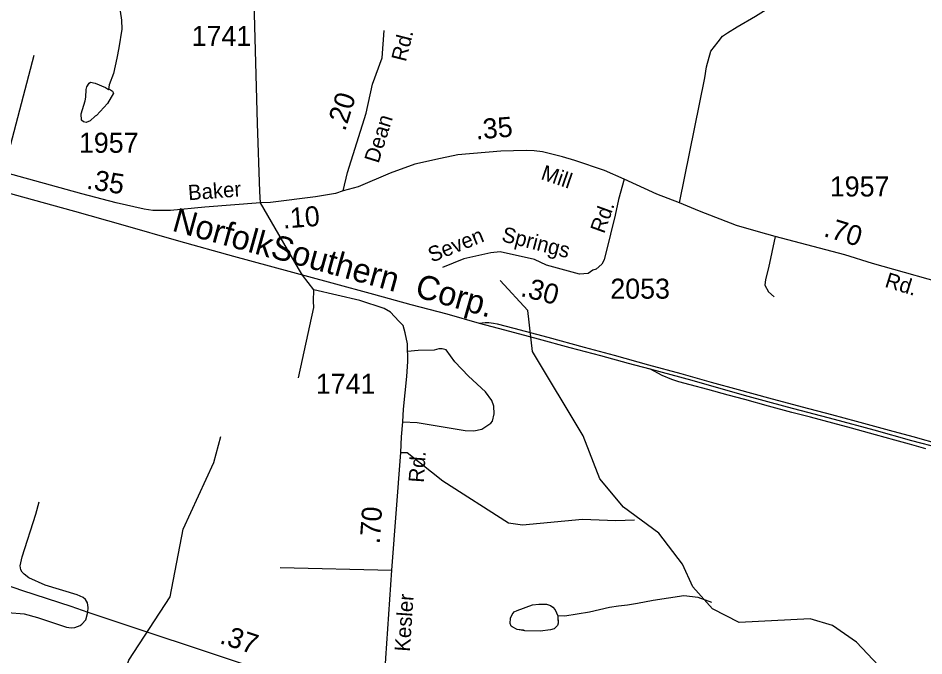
# Model space of a CAD drawing. Extents: x 1473865 to 1648260, y 639067 to 773536.
# Drawn here: x 1505606 to 1511254, y 721780 to 725760 of the extents above; entities that cross this region are included whole.
import ezdxf

# ---------------------------------------------------------------- set-up
doc = ezdxf.new("R2010")
doc.units = 0
for name, color, linetype in [('Exist Hydrographic Creek Single Shore', 7, 'Continuous'), ('Exist Hydrographic Misc Water Feature', 7, 'Continuous'), ('Exist Railroad Mainline', 7, 'Continuous'), ('Exist Railroad Mainline Label', 7, 'Continuous'), ('Exist Road Non-System Type 51', 7, 'Continuous'), ('Exist Road Primary US Attributed', 7, 'Continuous'), ('Exist Road Primary US Mileage Hundredths English Label', 7, 'Continuous'), ('Exist Road Secondary Mileage Hundredths English Label', 7, 'Continuous'), ('Exist Road Secondary Type 51 Attributed', 7, 'Continuous'), ('Exist Road Secondary Type 51 Label', 7, 'Continuous'), ('Exist Road Secondary Type 51 Number Label', 7, 'Continuous')]:
    doc.layers.add(name, color=color, linetype=linetype)

msp = doc.modelspace()

# ---------------------------------------------------------------- linework, layer by layer
at = {"layer": 'Exist Hydrographic Creek Single Shore'}
msp.add_lwpolyline([(1510972.3, 721721.4), (1510833.4, 721865.3), (1510685.3, 721970.1), (1510544.4, 722012.3), (1510102.4, 721988.4), (1509936.3, 722073.8), (1509814.4, 722210.9), (1509749.4, 722353.3), (1509602.4, 722546.6), (1509380.3, 722708.7), (1509233.4, 722885.6), (1509129.3, 723153.6), (1508813.3, 723678.7), (1508784.3, 723935.3), (1508612.4, 724122.6)], dxfattribs=at)
at = {"layer": 'Exist Hydrographic Misc Water Feature'}
for points in [[(1506242.9, 725802.3), (1506249.9, 725746.2), (1506252.8, 725690.1), (1506234.8, 725574.6), (1506221.7, 725510.9), (1506199.9, 725415.3), (1506174.6, 725343.9), (1506168.6, 725314.8)], [(1506168.6, 725314.8), (1506176.1, 725315.9), (1506194, 725303.5), (1506200.7, 725292), (1506162.5, 725226.2), (1506095.2, 725151.5), (1506087.1, 725147.7), (1506054.6, 725118.3), (1506030.5, 725108.8), (1506014.5, 725113.1), (1506000.7, 725123.3), (1505999.4, 725163.3), (1506024.8, 725242.8), (1506029.2, 725266.7), (1506030.1, 725314.6), (1506034.3, 725330.5), (1506048.8, 725354.3), (1506056.9, 725360.1), (1506086.8, 725353.5), (1506150.3, 725326.3), (1506168.6, 725314.8)], [(1506809.2, 713697.5), (1506731.2, 713991.2), (1506727.2, 714283.4), (1506386.2, 714772.9), (1506100.3, 716137.6), (1506090.2, 716502.2), (1506115.2, 717496.3), (1506265.2, 718451.7), (1506315.3, 718933.3), (1506320.3, 719268), (1506235.3, 719627.5), (1506154.2, 719770.3), (1506083.3, 720021.2), (1506054.2, 720271.3), (1506093.3, 720615.2), (1506216.2, 720993.5), (1506221.3, 721252.7), (1506206.3, 721387.5), (1506226.3, 721544.8), (1506296.3, 721753.4), (1506553.2, 722148.7), (1506635.3, 722570.5), (1506826.3, 722986.8), (1506870.2, 723150.1)], [(1508971.6, 722029.3), (1508971.6, 722013.2), (1508973.2, 721985.2), (1508968.8, 721969.3), (1508948.5, 721949.7), (1508926.4, 721942.1), (1508862.2, 721935.3), (1508766.3, 721937.1), (1508758.4, 721941.3), (1508718.4, 721946), (1508686.7, 721960.7), (1508680.8, 721966.8), (1508675, 721982.8), (1508675.6, 722014.8), (1508686.1, 722038.6), (1508700.3, 722054.3), (1508718.5, 722063.9), (1508813.1, 722098.1), (1508853.2, 722103.4), (1508901.2, 722102.4), (1508925.1, 722094), (1508940.9, 722083.7), (1508954.6, 722067.5), (1508971.6, 722029.3)], [(1508971.6, 722029.3), (1508973.2, 721985.2), (1508968.8, 721969.3), (1508948.5, 721949.7), (1508926.4, 721942.1), (1508862.2, 721935.3), (1508766.3, 721937.1), (1508718.4, 721946), (1508686.7, 721960.7), (1508680.8, 721966.8), (1508675, 721982.8), (1508675.6, 722014.8), (1508686.1, 722038.6), (1508700.3, 722054.3), (1508718.5, 722063.9), (1508813.1, 722098.1), (1508853.2, 722103.4), (1508901.2, 722102.4), (1508925.1, 722094), (1508940.9, 722083.7), (1508954.6, 722067.5), (1508971.6, 722029.3)], [(1509931.8, 722113.1), (1509846.2, 722144.5), (1509758.3, 722154.2), (1509565.8, 722125.9), (1509469.4, 722107.7), (1509405.2, 722096.9), (1509349.1, 722090), (1509292.9, 722083.1), (1509168.4, 722053.4), (1509015.9, 722028.4), (1508971.6, 722029.3)]]:
    msp.add_lwpolyline(points, dxfattribs=at)
at = {"layer": 'Exist Railroad Mainline'}
for points in [[(1505368.3, 724718.2), (1505633.1, 724644.2), (1505957.7, 724555.6), (1506258.5, 724469.3), (1506607.1, 724370.2), (1506949.6, 724275.2), (1507294.2, 724180.4), (1507563.1, 724108.6), (1507822, 724036.7), (1508055, 723973.4), (1508280.1, 723914.2), (1508481.3, 723857.3)], [(1508481.3, 723857.3), (1508518.8, 723861.2), (1508541.4, 723860.3), (1508569.7, 723856.9), (1508593.2, 723851.7), (1508696.8, 723826.2), (1508909.9, 723769), (1509135, 723705.9), (1509322.9, 723656.2), (1509537.4, 723596.1), (1509738.6, 723543.2), (1509927.8, 723488.4), (1510097.1, 723442.1), (1510286.4, 723391.3), (1510495.6, 723334.2), (1510678.9, 723285.7), (1510833.1, 723244), (1511037.3, 723188.4), (1511184.8, 723148.4), (1511362.1, 723099.8)], [(1508481.3, 723857.3), (1508638.7, 723814.9), (1508849.9, 723758), (1509047.1, 723705.2), (1509238.4, 723654.3), (1509409.5, 723607.9), (1509545.1, 723571.9)], [(1511265.7, 723073.1), (1511164, 723100.6), (1511072.5, 723126.1), (1510952.9, 723159.7), (1510802.6, 723200.4), (1510686, 723231.5), (1510547.1, 723268.9), (1510431, 723299.3), (1510285.6, 723339.3), (1510138.3, 723379.4), (1510034.6, 723407), (1509907.3, 723442.7), (1509797.6, 723472.4), (1509726, 723491.4), (1509682, 723505.9), (1509622.5, 723530.9), (1509545.1, 723571.9)], [(1509545.1, 723571.9), (1509808, 723500.2), (1510132.7, 723407.6), (1510401.5, 723333.7), (1510695.5, 723256.7), (1510943.3, 723189.9), (1511176.5, 723124.6), (1511353.6, 723078), (1511558.8, 723019), (1511731.1, 722972.3), (1511855.7, 722938.8), (1512009, 722898.9), (1512118.6, 722868.8), (1512228.1, 722839.4), (1512327.8, 722812)]]:
    msp.add_lwpolyline(points, dxfattribs=at)
at = {"layer": 'Exist Road Non-System Type 51'}
for p, q in [((1505514.2, 724798.1), (1505706.4, 725529.2)), ((1507240.3, 722331.1), (1507936.9, 722315.8))]:
    msp.add_line(p, q, dxfattribs=at)
for points in [[(1509731.3, 724607.2), (1509889.3, 725386.6), (1509899.2, 725456.3), (1509924.8, 725553.8), (1509972.5, 725612.1), (1509999, 725647.8), (1510030, 725669), (1510089.7, 725704.6), (1510204.8, 725771.4), (1510327.1, 725849.7), (1510499.9, 725960.2), (1510875.2, 726202), (1511051.4, 726324.4), (1511088.4, 726354.2), (1511133.9, 726395.5), (1511173.1, 726485.8), (1511181.9, 726547.6), (1511185.8, 726680.2), (1511193.6, 726859), (1511191.7, 727024.9), (1511205.7, 727329.3)], [(1510327.9, 724397.2), (1510286, 724200.7), (1510266.7, 724128.3), (1510263.5, 724092.8), (1510284.4, 724051), (1510319.8, 724020.4)], [(1507354.2, 723516.3), (1507450.9, 723954.9), (1507447.9, 723994.2), (1507451, 724065)], [(1508004.2, 723241.2), (1508094.2, 723235.8), (1508393.5, 723187.7), (1508447.3, 723184.9), (1508497.5, 723194.3), (1508554.1, 723233.3), (1508564.2, 723245.3), (1508574.9, 723291.1), (1508573.5, 723339.2), (1508560, 723373.3), (1508520.9, 723428.6), (1508415.1, 723525.4), (1508330.4, 723616.1), (1508303.2, 723652.4), (1508274.4, 723689.2), (1508250.5, 723695.7), (1508230.5, 723695.9), (1508200.3, 723688.3), (1508100.7, 723685.7), (1508034.2, 723679.7)], [(1507992.7, 723050), (1508031.2, 723050), (1508254.8, 722872.5), (1508663.4, 722610.1), (1508752.1, 722598.6), (1509126.1, 722633.3), (1509334.2, 722625.6), (1509449.9, 722629.4)], [(1506040, 722053), (1506041.8, 722081.6), (1506038.4, 722111.7), (1506026.6, 722131.9), (1506010.9, 722144.3), (1505973.2, 722160.8), (1505774.3, 722222.1), (1505673, 722267.9), (1505643.4, 722290.4), (1505631.7, 722302.6), (1505623.8, 722316.8), (1505618.3, 722342.7), (1505631.2, 722398.5), (1505715.6, 722665.1), (1505736.8, 722740.7)]]:
    msp.add_lwpolyline(points, dxfattribs=at)
at = {"layer": 'Exist Road Primary US Attributed'}
for points in [[(1503181.7, 723021.6), (1503536.3, 722902.2), (1504318.6, 722637.3), (1504517.7, 722580.2), (1504564.7, 722564.5), (1505188.3, 722343), (1505634, 722188.7), (1505934.6, 722091), (1506040, 722053)], [(1506040, 722053), (1507097.1, 721702.1), (1507789.7, 721464.4), (1507881.3, 721435.2)]]:
    msp.add_lwpolyline(points, dxfattribs=at)
at = {"layer": 'Exist Road Secondary Type 51 Attributed'}
for points in [[(1507117.3, 724607.4), (1507112.4, 724677.6), (1507098.1, 725101.7), (1507065.1, 726319.8), (1507058.9, 726452), (1507059.4, 726486), (1507066.3, 726549.9), (1507078.4, 726639), (1507093.8, 726718.3), (1507128.3, 726802.2), (1507153, 726849.8), (1507215.9, 726957.1), (1507303.5, 727078.4), (1507631.9, 727569.8), (1507894.8, 727943.9), (1508024.1, 728128), (1508391.7, 728684.9)], [(1507632.8, 724682.2), (1507660, 724796.2), (1507776.5, 725165.8), (1507816.4, 725347.6), (1507875.2, 725513.1), (1507889.5, 725682.2)], [(1509386.1, 724755), (1509261.7, 724809.1), (1509078.7, 724871.8), (1509001.1, 724894.8), (1508875.4, 724924.5), (1508824.8, 724932.2), (1508773.6, 724934), (1508615.4, 724929.1), (1508347.2, 724906.9), (1508239.1, 724883.6), (1508079.1, 724848.7), (1507926.8, 724793), (1507726.1, 724707.4), (1507632.8, 724682.2)], [(1507117.3, 724607.4), (1506769.4, 724581.2), (1506556.7, 724559.3), (1506446.8, 724558.9), (1506391, 724567.7), (1506217.5, 724608.2), (1506004.3, 724663.1), (1505514.2, 724798.1)], [(1509386.1, 724755), (1509350.7, 724627.9), (1509328.2, 724529.8), (1509299.3, 724411.5), (1509260, 724251.2), (1509245.7, 724225.5), (1509211.3, 724194), (1509190, 724186.3), (1509161.1, 724165.4), (1509106.4, 724162.1), (1508901.2, 724218.4), (1508825.2, 724253.8), (1508613, 724302.5), (1508554.8, 724295.3), (1508386.3, 724257.7), (1508252.3, 724203.5)], [(1512599.7, 723546.3), (1512526.7, 723585.8), (1512363.6, 723682.9), (1512246.6, 723747.3), (1512119.4, 723811.1), (1511959.3, 723889), (1511735.8, 723986.9), (1511595.7, 724035.2), (1511480.4, 724074.4), (1510933.5, 724229.7), (1510762.2, 724282.1), (1510327.9, 724397.2), (1510223.3, 724426.2), (1510085.8, 724465.5), (1509855.1, 724554.6), (1509731.3, 724607.2), (1509589.2, 724661.8), (1509386.1, 724755)], [(1507632.8, 724682.2), (1507585.9, 724666.5), (1507460, 724645.3), (1507179.4, 724608.6), (1507117.3, 724607.4)], [(1507378.9, 724155.7), (1507355.5, 724196.6), (1507117.3, 724607.4)], [(1507881.3, 721435.2), (1507899.8, 721767), (1507936.9, 722315.8), (1507992.7, 723050), (1507997.6, 723148.2), (1508004.2, 723241.2), (1508009.4, 723319.2), (1508030.1, 723522.7), (1508035.4, 723616.6), (1508035, 723726.7), (1508020.1, 723796.1), (1508006.4, 723841), (1507979.7, 723868.6), (1507927.6, 723925.7), (1507888.6, 723947.3), (1507736.8, 723998.8), (1507451, 724065), (1507378.9, 724155.7)], [(1505541.6, 722052.1), (1505643.2, 722042.4), (1505726.8, 722018.9), (1505907.9, 721959.8), (1505935.8, 721955.5), (1505959.9, 721957), (1505992, 721970.6), (1506004.1, 721978.3), (1506028.7, 722005.8), (1506040, 722053)]]:
    msp.add_lwpolyline(points, dxfattribs=at)

# ---------------------------------------------------------------- texts
at = {"layer": 'Exist Railroad Mainline Label'}
for s, rotation, p in [('Norfolk', 344.5017, (1506559.7, 724434.4)), ('Southern', 344.4864, (1507173.3, 724267.9)), ('Corp.', 344.2091, (1508073.6, 724023.8))]:
    msp.add_text(s, height=150, rotation=rotation, dxfattribs=at).set_placement(p)
at = {"layer": 'Exist Road Primary US Mileage Hundredths English Label'}
msp.add_text('.37', height=125, rotation=341.6356, dxfattribs=at).set_placement((1506856.6, 721861.1))
at = {"layer": 'Exist Road Secondary Mileage Hundredths English Label'}
for s, rotation, p in [('.20', 72.6383, (1507644.5, 725049.5)), ('.35', 4.7324, (1508462.4, 725002.3)), ('.35', 351.0187, (1506027.7, 724696)), ('.10', 4.3416, (1507259.3, 724446.6)), ('.70', 342.9599, (1510623.6, 724400.9)), ('.30', 345.5636, (1508733.7, 724027.3)), ('.70', 85.9492, (1507860.3, 722475.9))]:
    msp.add_text(s, height=125, rotation=rotation, dxfattribs=at).set_placement(p)
at = {"layer": 'Exist Road Secondary Type 51 Label'}
for s, rotation, p in [('Rd.', 75.8928, (1508023.8, 725483.4)), ('Dean', 72.6382, (1507853.2, 724849.4)), ('Mill', 341.0827, (1508860.2, 724756.5)), ('Baker', 4.3062, (1506668.9, 724623)), ('Rd.', 70.2125, (1509260.3, 724410.7)), ('Seven', 22.0134, (1508185.8, 724233.7)), ('Springs', 345.5633, (1508615.8, 724368.9)), ('Rd.', 342.9599, (1511005.5, 724084.4)), ('Rd.', 85.949, (1508135.2, 722859)), ('Kesler', 85.9491, (1508048, 721804.5))]:
    msp.add_text(s, height=95, rotation=rotation, dxfattribs=at).set_placement(p)
at = {"layer": 'Exist Road Secondary Type 51 Number Label'}
for s, p in [('1741', (1506687.9, 725586.2)), ('1957', (1505985.2, 724919.8)), ('1957', (1510667.9, 724647)), ('2053', (1509298.9, 724009.2)), ('1741', (1507462.5, 723415.7))]:
    msp.add_text(s, height=125, dxfattribs=at).set_placement(p)

doc.saveas('drawing.dxf')
